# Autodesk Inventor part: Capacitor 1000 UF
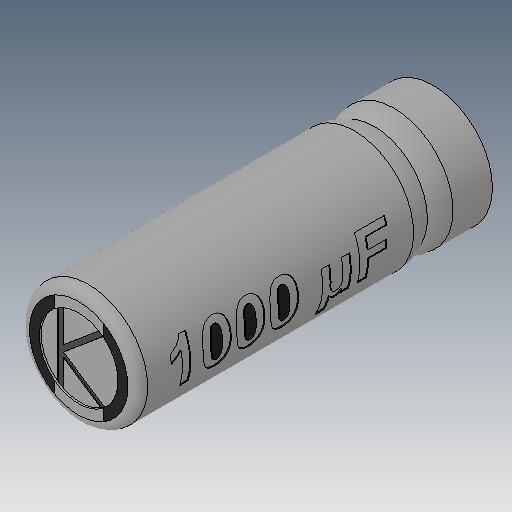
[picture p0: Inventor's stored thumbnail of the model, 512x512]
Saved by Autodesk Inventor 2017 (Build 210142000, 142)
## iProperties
Created: 2005-12
Part Number: Capacitor 1000 UF
Material: Generic
Document SubType Name: Modeling
Designer: DanielSeverino
Density: 1 g/cm^3
Appearance: Default
Author: DanielSeverino
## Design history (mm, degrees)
feature "Solid1"
body "Solid2"
